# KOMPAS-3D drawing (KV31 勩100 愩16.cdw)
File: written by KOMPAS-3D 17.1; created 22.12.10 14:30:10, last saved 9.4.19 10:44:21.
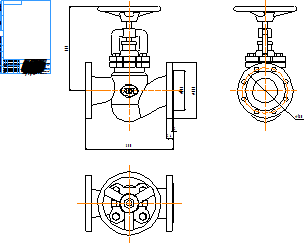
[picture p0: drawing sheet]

Title block, sheet 1: name: KV31 Ду100 Ру16; material: Внимание! Данный продукт является объектом авторского права ООО «Торговый Дом АДЛ». / Запрещается изменение, копирование, распространение / (в том числе путем копирования на другие сайты и ресурсы в Интернете) / или любое иное использование информации и объектов без предварительного / согласия правообладателя (ООО «Торговый Дом АДЛ»).; mass: 38; scale: 1:1; sheets: 1; organisation: ООО "Торговый дом АДЛ"; sheet format: A4; stored path: \\adlc.lan\data\АДЛ_ПКД\3D-модели\ADL production\Вентили ГРАНВЕНТ\KV31\KOMPAS 2D\KV31 Ду100.cdw

Views: Спереди 1, Проекционный вид 2, Проекционный вид 3
Dimensions and other numbers on the sheet: 156; 220; 2; 24; 350; 339; 180; 1:1; 1; 38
